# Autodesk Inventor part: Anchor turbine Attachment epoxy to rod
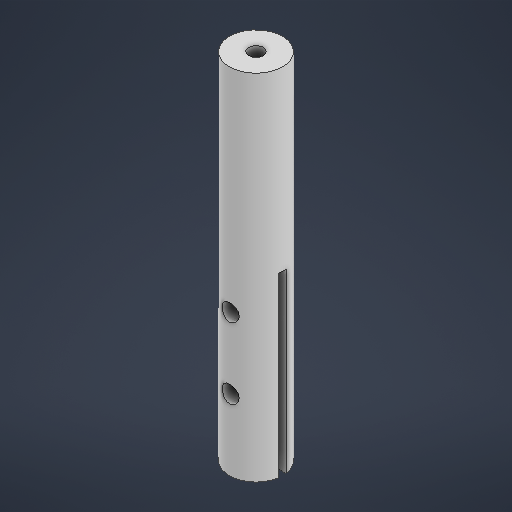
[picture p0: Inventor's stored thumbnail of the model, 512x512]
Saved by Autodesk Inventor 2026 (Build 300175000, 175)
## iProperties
Created: 2025-10
Part Number: Anchor turbine Attachment epoxy to rod
Material: Generic
Document SubType Name: Modeling
Designer: sab273
Density: 1 g/cm^3
Appearance: Default
Author: sab273
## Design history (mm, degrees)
sketch "Sketch1"
  geometry: C1 r 7.5 at (0, 0); 1 further point
  constraints: 1 centre point, 1 coincident
  dimensions: "d0" = 15 diameter of C1
extrude "Extrusion1" new body sketch "Sketch1" distance "d1" = 100; taper "d2" = 0 deg
sketch "Sketch4"
  geometry: 1 further point
sketch "Sketch5"
  geometry: L1 (-7.426, 1.05)-(7.426, 1.05); L2 (-7.426, -1.05)-(7.426, -1.05); A1 r 7.5 centre (0, 0) between (-7.426, 1.05) and (-7.426, -1.05) reference; 1 further point
  constraints: 4 end point, 4 point on circle
extrude "Extrusion4" cut sketch "Sketch5" distance "d12" = 50; taper "d13" = 0 deg
sketch "Sketch10"
  geometry: C1 r 2.4 at (7.426, 20); C2 r 2.4 at (7.426, 40); 1 further point
  constraints: 2 centre point
extrude "Extrusion6" cut sketch "Sketch10" distance "d22" = 7.5; taper "d23" = 0 deg
sketch "Sketch11"
  geometry: C1 r 2.4 at (7.426, 20); C2 r 2.4 at (7.426, 40); 1 further point
  constraints: 2 centre point
extrude "Extrusion7" cut sketch "Sketch11" distance "d28" = 7.5; taper "d29" = 0 deg
sketch "Sketch12"
  geometry: C1 r 2.05 at (0, 0); 1 further point
  constraints: 1 centre point, 1 coincident
  dimensions: "d30" = 4.1 diameter of C1
extrude "Extrusion8" cut sketch "Sketch12" distance "d31" = 30; taper "d32" = 0 deg
body "Solid1"
